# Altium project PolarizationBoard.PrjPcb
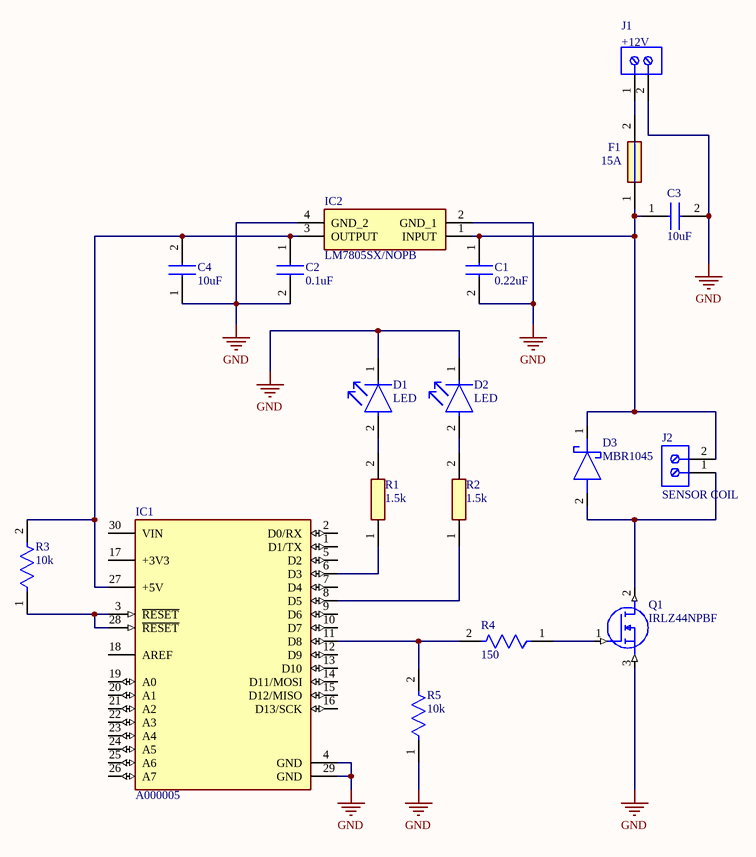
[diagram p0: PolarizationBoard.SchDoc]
1 sheet, 18 parts. Net scope: global (net labels, ports and power ports of the same name join across sheets).
Board file: PolarizationBoard.PcbDoc

## Sheet PolarizationBoard.SchDoc
size A; SheetNumber: 1; SheetTotal: 1

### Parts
C1  0.22uF  [CAPC1005X55N]
C2  0.1uF  [CAPC1005X55N]
C3  10uF  [CAPC3225X280N]
C4  10uF  [CAPC3225X280N]
D1  LED  [FP-6_544-5255_01-4-MFG]
D2  LED  [FP-LTL-1CHEE-MFG]
D3  MBR1045  [MBR1045]
F1  15A  [0697H915002]
IC1  A000005  [FP-A000005-MFG]
IC2  LM7805SX/NOPB  [KTT0003B]
J1  +12V  [691213710002]
J2  SENSOR COIL  [691213710002]
Q1  IRLZ44NPBF  [TO254P469X1042X1967-3P]
R1  1.5k  [ERA6AEB101V]
R2  1.5k  [ERA6AEB101V]
R3  10k  [FP-AC0603-IPC_A]
R4  150  [FP-RG1608-IPC_A]
R5  10k  [FP-AC0603-IPC_A]

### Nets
GND: C1.2 C2.2 C3.2 C4.1 D1.1(C) D2.1(C) IC1.4(GND) IC1.29(GND) IC2.2(GND_1) IC2.4(GND_2) J1.2 Q1.3(S) R5.1
NetC1_1: C1.1 C3.1 D3.1(K) F1.1 IC2.1(INPUT) J2.2
NetC2_1: C2.1 C4.2 IC1.27(+5V) IC2.3(OUTPUT) R3.2
NetD1_2: D1.2(A) R1.2
NetD2_2: D2.2(A) R2.2
NetD3_2: D3.2(A) J2.1 Q1.2(D)
NetF1_2: F1.2 J1.1
NetIC1_3: IC1.3(~{RESET}) IC1.28(~{RESET}) R3.1
NetIC1_6: IC1.6(D3) R1.1
NetIC1_8: IC1.8(D5) R2.1
NetIC1_11: IC1.11(D8) R4.2 R5.2
NetQ1_1: Q1.1(G) R4.1

Not connected (* = marked no-connect by the designer): IC1 1(D1/TX) 2(D0/RX) 5(D2) 7(D4) 9(D6) 10(D7) 12(D9) 13(D10) 14(D11/MOSI) 15(D12/MISO) 16(D13/SCK) 17(+3V3) 18(AREF) 19(A0) 20(A1) 21(A2) 22(A3) 23(A4) 24(A5) 25(A6) 26(A7) 30(VIN)

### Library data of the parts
C1 = MLASU105SB5224KFNA01: MLASU105SB5224KFNA01 MSASU105SB5224KFNA01; Manufacturer_Name: TAIYO YUDEN
C2 = MCASU105SB5104MFNA01: MCASU105SB5104MFNA01 CGA2B3X5R1H104M050BB; Manufacturer_Name: TAIYO YUDEN
C3 C4 = MCASU32MAB7106KPNA1J: MCASU32MAB7106KPNA1J MSASU32MAB7106KPNA01; Manufacturer_Name: TAIYO YUDEN
D1 = CMP-00030-55433990-1: TLLG4400 (G); Lens Transparency: Diffused; Dominant Wavelength: 575nm; Test Current: 2mA; Viewing Angle: 50°; Color: Green; Power Dissipation: 20mW; Lens Style: Circular, Colored, Diffused, Dome, Round; Forward Voltage: 1.9V; Number of LEDs: 1; Voltage Rating (DC): 2.4V; Lens Size: 3mm; Luminous Intensity: 1.2mcd; Reverse Voltage: 20V
D2 = CMP-22017-000040-1: LTL-1CHEE (R); Viewing Angle: 45°; Lens Transparency: Clear; Illumination Color: Red; Power Dissipation: 100mW; Wavelength: 635nm; Number of LEDs: 1; Test Current: 10mA; Lens Style: Dome; Forward Current: 30mA; Forward Voltage: 2V; Luminous Intensity: 19mcd; Reverse Voltage: 5V; Dominant Wavelength: 625nm
D3 = MBR1045: Schottky Diode; Manufacturer_Name: onsemi
F1 = 0697H9150-02: Manufacturer_Name: BelFuse
IC1 = CMP-189986-000002-1: ARDUINO NANO ATMEGA328 EVAL BRD; Number of Bits: 8; Evaluation Kit: Yes; Operating Supply Voltage: 12V; Interface: I2C; Data Bus Width: 8b; Core Architecture: AVR
IC2 = LM7805SX_NOPB: Integrated Circuit; Manufacturer_Name: Texas Instruments
J1 J2 = CMP-1502-02526-3: 691213710002; Voltage: 300V; Number of Positions Per Level: 2; Pitch: 5.0038mm; Current: 10A; Plating: Brass, Steel; Wire Gauge (Min): 16AWG; Wire Gauge (Max): 26AWG; Stripping Length: -7mm; Number of Levels: 1
Q1 = IRLZ44NPBF: MOSFET (N-Channel); Manufacturer_Name: Infineon
R1 R2 = ERA-6AED152V: Manufacturer_Name: Panasonic
R3 R5 = CMP-03412-040683-1: AC0603JR-7W10KL
R4 = CMP-28537-000042-1: RG1608N-151-W-T5 RG1608N-151-W-T1; Resistance: 150R; Power Rating: 62.5mW; Temperature Coefficient: 10ppm/°C; Voltage Rating (DC): 75V; Max Power Dissipation: 100mW; Tolerance: 0.05%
